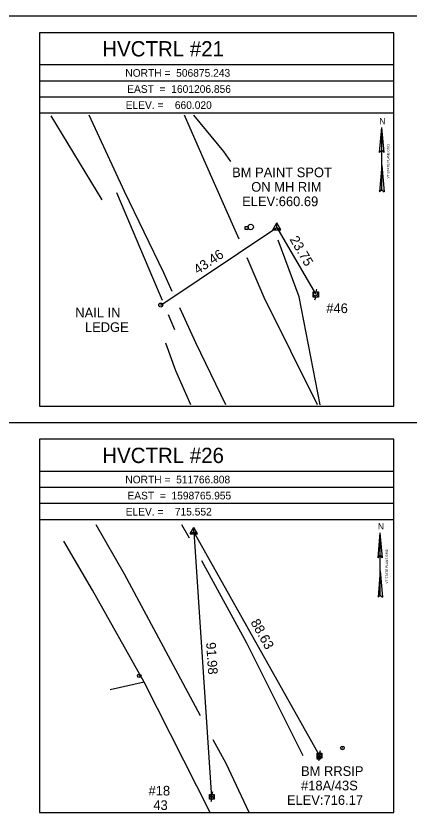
# Model space of a CAD drawing. Extents: x 1598730 to 1599370, y 501440 to 502728.
# Drawn here: x 1598877.2 to 1598999.5, y 501610.1 to 501860.2 of the extents above; entities that cross this region are included whole.
import ezdxf

# ---------------------------------------------------------------- set-up
doc = ezdxf.new("R2010")
doc.units = 0
for name, color, linetype in [('C_C', 7, 'Continuous'), ('CBP', 7, 'Continuous'), ('CPBM', 7, 'Continuous'), ('CPSM', 7, 'Continuous'), ('Default', 7, 'Continuous'), ('LABL', 7, 'Continuous'), ('LARO', 7, 'Continuous'), ('LAWA', 7, 'Continuous'), ('LWS', 7, 'Continuous'), ('MPIP', 7, 'Continuous'), ('NBL1', 7, 'Continuous'), ('NBL2', 7, 'Continuous'), ('NNA_P', 7, 'Continuous'), ('PET', 7, 'Continuous'), ('RDG', 7, 'Continuous'), ('U_C', 7, 'Continuous'), ('UP', 7, 'Continuous'), ('UPGW', 7, 'Continuous'), ('UTMH', 7, 'Continuous')]:
    doc.layers.add(name, color=color, linetype=linetype)

msp = doc.modelspace()

# ---------------------------------------------------------------- linework, layer by layer
at = {"layer": 'CBP'}
for centre, radius in [((1598970.18, 501773.95), 0.625), ((1598970.18, 501773.95), 0.0833), ((1598922.16, 501770.42), 0.625), ((1598922.16, 501770.42), 0.0833), ((1598971.48, 501630.4), 0.562), ((1598971.48, 501630.4), 0.075), ((1598937.91, 501617.36), 0.562), ((1598937.91, 501617.36), 0.075)]:
    msp.add_circle(centre, radius, dxfattribs=at)
at = {"layer": 'CPBM'}
for p, q in [((1598948.35, 501793.85), (1598948.35, 501794.85)), ((1598948.35, 501794.85), (1598949.35, 501794.85)), ((1598949.35, 501794.85), (1598949.35, 501793.85)), ((1598949.35, 501793.85), (1598948.35, 501793.85)), ((1598948.86, 501794.35), (1598948.86, 501794.35)), ((1598948.86, 501794.35), (1598948.86, 501794.35)), ((1598970.73, 501629.34), (1598970.73, 501630.24)), ((1598970.73, 501630.24), (1598971.63, 501630.24)), ((1598971.18, 501629.79), (1598971.18, 501629.79)), ((1598971.18, 501629.79), (1598971.18, 501629.79)), ((1598971.63, 501630.24), (1598971.63, 501629.34)), ((1598971.63, 501629.34), (1598970.73, 501629.34))]:
    msp.add_line(p, q, dxfattribs=at)
at = {"layer": 'CPSM'}
for p, q in [((1598956.98, 501793.76), (1598958.23, 501795.93)), ((1598959.48, 501793.76), (1598958.23, 501795.93)), ((1598958.23, 501794.48), (1598958.23, 501795.93)), ((1598956.98, 501793.76), (1598958.23, 501794.48)), ((1598956.98, 501793.76), (1598959.48, 501793.76)), ((1598958.23, 501794.48), (1598958.23, 501794.48)), ((1598958.23, 501794.48), (1598959.48, 501793.76)), ((1598931.33, 501699.33), (1598932.46, 501701.27)), ((1598931.33, 501699.33), (1598932.46, 501699.97)), ((1598933.58, 501699.33), (1598932.46, 501701.27)), ((1598932.46, 501699.97), (1598932.46, 501701.27)), ((1598932.46, 501699.97), (1598932.46, 501699.97)), ((1598932.46, 501699.97), (1598933.58, 501699.33)), ((1598931.33, 501699.33), (1598933.58, 501699.33))]:
    msp.add_line(p, q, dxfattribs=at)
at = {"layer": 'Default'}
for p, q in [((1598922.16, 501770.42), (1598958.23, 501794.48)), ((1598958.23, 501794.48), (1598970.18, 501773.95)), ((1598971.48, 501630.4), (1598932.46, 501699.97)), ((1598932.46, 501699.97), (1598937.91, 501617.36))]:
    msp.add_line(p, q, dxfattribs=at)
at = {"layer": 'LABL'}
msp.add_lwpolyline([(1598937.48, 501612.71), (1598916.99, 501653.19), (1598900.97, 501681.85), (1598892.1, 501697.06)], dxfattribs=at)
at = {"layer": 'LARO'}
for points in [[(1598922.7, 501771.87), (1598919.74, 501778.91), (1598908.56, 501805.32)], [(1598926.53, 501762.76), (1598924.6, 501767.35)]]:
    msp.add_lwpolyline(points, dxfattribs=at)
at = {"layer": 'LAWA'}
for points in [[(1598903.97, 501803.15), (1598888.17, 501829.26)], [(1598931.46, 501739.39), (1598926.87, 501749.94), (1598923.74, 501758.54)]]:
    msp.add_lwpolyline(points, dxfattribs=at)
at = {"layer": 'LWS'}
msp.add_lwpolyline([(1598916.99, 501653.19), (1598906.41, 501650.81)], dxfattribs=at)
at = {"layer": 'MPIP'}
for radius in [0.562, 0.075]:
    msp.add_circle((1598915.48, 501655.2), radius, dxfattribs=at)
at = {"layer": 'NBL1'}
msp.add_lwpolyline([(1598729.53, 501440.21), (1599369.53, 501440.21), (1599369.53, 501860.21), (1598729.53, 501860.21)], close=True, dxfattribs=at)
at = {"layer": 'NBL2'}
for p, q in [((1598994.53, 501845.04), (1598884.53, 501845.04)), ((1598994.53, 501840.04), (1598884.53, 501840.04)), ((1598994.53, 501835.04), (1598884.53, 501835.04)), ((1598994.53, 501830.04), (1598884.53, 501830.04)), ((1598729.53, 501733.88), (1599369.53, 501733.88)), ((1598994.53, 501718.71), (1598884.53, 501718.71)), ((1598994.53, 501713.71), (1598884.53, 501713.71)), ((1598994.53, 501708.71), (1598884.53, 501708.71)), ((1598994.53, 501703.71), (1598884.53, 501703.71))]:
    msp.add_line(p, q, dxfattribs=at)
for points in [[(1598884.53, 501739.04), (1598994.53, 501739.04), (1598994.53, 501855.04), (1598884.53, 501855.04)], [(1598884.53, 501612.71), (1598994.53, 501612.71), (1598994.53, 501728.71), (1598884.53, 501728.71)]]:
    msp.add_lwpolyline(points, close=True, dxfattribs=at)
at = {"layer": 'NNA_P'}
for p, q in [((1598990.11, 501817.8), (1598990.81, 501825.6)), ((1598990.81, 501806.22), (1598990.81, 501825.6)), ((1598991.5, 501817.8), (1598990.81, 501825.6)), ((1598990.11, 501817.8), (1598990.81, 501818.57)), ((1598991.5, 501817.8), (1598990.81, 501818.57)), ((1598990.81, 501813.75), (1598990.09, 501805.58)), ((1598990.81, 501813.75), (1598991.53, 501805.58)), ((1598990.81, 501806.22), (1598990.09, 501805.58)), ((1598990.81, 501806.22), (1598991.53, 501805.58)), ((1598989.65, 501691.89), (1598990.35, 501699.68)), ((1598990.35, 501680.31), (1598990.35, 501699.68)), ((1598991.04, 501691.89), (1598990.35, 501699.68)), ((1598989.65, 501691.89), (1598990.35, 501692.66)), ((1598991.04, 501691.89), (1598990.35, 501692.66)), ((1598990.35, 501687.84), (1598989.63, 501679.67)), ((1598990.35, 501687.84), (1598991.07, 501679.67)), ((1598990.35, 501680.31), (1598989.63, 501679.67)), ((1598990.35, 501680.31), (1598991.07, 501679.67))]:
    msp.add_line(p, q, dxfattribs=at)
at = {"layer": 'PET'}
for points in [[(1598925.74, 501774.61), (1598923.07, 501780.46), (1598910.87, 501805.67), (1598899.9, 501829.4)], [(1598946.51, 501790.86), (1598945.68, 501792.79), (1598935.67, 501815.39), (1598929.58, 501829.4)], [(1598970.79, 501739.39), (1598954.31, 501772.81), (1598949.02, 501785.05)], [(1598942.34, 501739.39), (1598933.03, 501758.68), (1598928.05, 501769.57)], [(1598934.54, 501642.74), (1598926.89, 501657.05), (1598910.94, 501686.8), (1598902.08, 501702.12)], [(1598931.06, 501698.01), (1598928.75, 501702.12)], [(1598966.37, 501630.37), (1598948.93, 501665.36), (1598934.96, 501690.92)], [(1598949.57, 501612.71), (1598942.44, 501627.94), (1598938.48, 501635.36)]]:
    msp.add_lwpolyline(points, dxfattribs=at)
at = {"layer": 'RDG'}
for points in [[(1598943.89, 501815.06), (1598941.72, 501818.15), (1598932.47, 501829.4)], [(1598971.68, 501739.39), (1598965.16, 501773.02), (1598958.6, 501790.63)]]:
    msp.add_lwpolyline(points, dxfattribs=at)
at = {"layer": 'UP'}
for p, q in [((1598970.56, 501775.35), (1598970.31, 501774.51)), ((1598969.48, 501772.85), (1598969.48, 501774.51)), ((1598969.48, 501774.51), (1598971.15, 501774.51)), ((1598971.15, 501772.85), (1598969.48, 501772.85)), ((1598970.06, 501772.01), (1598970.31, 501772.85)), ((1598970.31, 501773.68), (1598970.31, 501773.68)), ((1598971.15, 501774.51), (1598971.15, 501772.85)), ((1598970.71, 501629.65), (1598970.71, 501631.15)), ((1598970.71, 501631.15), (1598972.21, 501631.15)), ((1598971.69, 501631.9), (1598971.46, 501631.15)), ((1598971.46, 501630.4), (1598971.46, 501630.4)), ((1598972.21, 501631.15), (1598972.21, 501629.65)), ((1598972.21, 501629.65), (1598970.71, 501629.65)), ((1598971.24, 501628.9), (1598971.46, 501629.65)), ((1598937.27, 501616.86), (1598937.27, 501618.36)), ((1598937.27, 501618.36), (1598938.77, 501618.36)), ((1598938.25, 501619.11), (1598938.02, 501618.36)), ((1598938.02, 501617.61), (1598938.02, 501617.61)), ((1598938.77, 501618.36), (1598938.77, 501616.86)), ((1598938.77, 501616.86), (1598937.27, 501616.86)), ((1598937.8, 501616.11), (1598938.02, 501616.86))]:
    msp.add_line(p, q, dxfattribs=at)
for centre, radius in [((1598970.31, 501773.68), 0.833), ((1598971.46, 501630.4), 0.75), ((1598938.02, 501617.61), 0.75)]:
    msp.add_circle(centre, radius, dxfattribs=at)
at = {"layer": 'UPGW'}
for radius in [0.562, 0.075]:
    msp.add_circle((1598978.57, 501632.81), radius, dxfattribs=at)
at = {"layer": 'UTMH'}
for p, q in [((1598950.09, 501794.67), (1598950.09, 501794.67)), ((1598950.92, 501794.67), (1598950.92, 501794.67))]:
    msp.add_line(p, q, dxfattribs=at)
msp.add_circle((1598950.09, 501794.67), 0.833, dxfattribs=at)

# ---------------------------------------------------------------- texts
at = {"layer": 'C_C'}
for s, p in [('BM PAINT SPOT', (1598944.32, 501810.15)), ('ON MH RIM', (1598950.26, 501805.65)), ('ELEV:660.69', (1598947.43, 501801.15)), ('NAIL IN', (1598895.62, 501766.56)), ('LEDGE', (1598898.61, 501762.06))]:
    msp.add_text(s, height=3, dxfattribs=at).set_placement(p)
at = {"layer": 'Default'}
for s, rotation, p in [('23.75', 300.1797, (1598962.09, 501790.84)), ('43.46', 33.7128, (1598933.65, 501779.88)), ('88.63', 299.2856, (1598949.96, 501671.84)), ('91.98', 273.7776, (1598936.24, 501665.54))]:
    msp.add_text(s, height=3, rotation=rotation, dxfattribs=at).set_placement(p)
at = {"layer": 'NBL2'}
for s, height, p in [('     HVCTRL #21    ', 4.75, (1598895.18, 501847.67)), ('NORTH =  506875.243 ', 2.375, (1598911.15, 501841.36)), ('EAST  =  1601206.856', 2.375, (1598911.74, 501836.36)), ('ELEV. =    660.020  ', 2.375, (1598911.26, 501831.36)), ('     HVCTRL #26    ', 4.75, (1598895.18, 501721.33)), ('NORTH =  511766.808 ', 2.375, (1598911.15, 501715.02)), ('EAST  =  1598765.955', 2.375, (1598911.81, 501710.02)), ('ELEV. =    715.552  ', 2.375, (1598911.26, 501705.02))]:
    msp.add_text(s, height=height, dxfattribs=at).set_placement(p)
at = {"layer": 'NNA_P'}
for p in [(1598990.04, 501826.61), (1598989.58, 501700.7)]:
    msp.add_text('N', height=1.97, dxfattribs=at).set_placement(p)
for p in [(1598993.16, 501809.78), (1598992.7, 501683.87)]:
    msp.add_text('VT STATE PLANE GRID', height=0.7, rotation=90.0204, dxfattribs=at).set_placement(p)
at = {"layer": 'U_C'}
for s, p in [('#46', (1598973.57, 501767.92)), ('BM RRSIP', (1598965.72, 501624.11)), ('#18A/43S', (1598965.73, 501619.61)), ('#18', (1598918.37, 501618.02)), ('ELEV:716.17', (1598961.34, 501615.11)), ('43', (1598919.86, 501613.52))]:
    msp.add_text(s, height=3, dxfattribs=at).set_placement(p)

doc.saveas('drawing.dxf')
